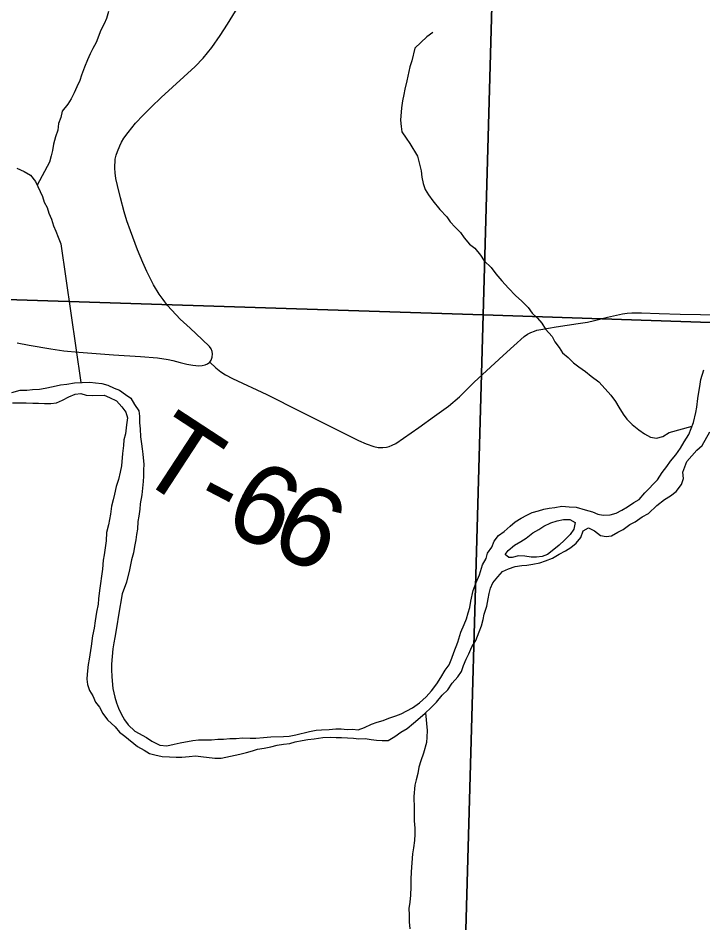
# Model space of a CAD drawing. Extents: x -3.3 to 34, y 0 to 56.8.
# Drawn here: x -1.696 to -1.207, y 30.269 to 30.915 of the extents above; entities that cross this region are included whole.
import ezdxf

# ---------------------------------------------------------------- set-up
doc = ezdxf.new("R2010")
doc.units = 0
for name, color, linetype in [('GM_X_Corporation', 7, 'Continuous'), ('GM_X_Major_River', 7, 'Continuous'), ('GM_X_State_Route', 7, 'Continuous'), ('GM_X_Township_Road', 7, 'Continuous'), ('GM_X_Township_Road_Text', 7, 'Continuous'), ('GT_Project_Soil_Layers', 7, 'Continuous')]:
    doc.layers.add(name, color=color, linetype=linetype)

msp = doc.modelspace()

# ---------------------------------------------------------------- linework, layer by layer
at = {"layer": 'GM_X_Corporation'}
for points in [[(-1.33537, 31.71163), (-1.36367, 30.70347), (-2.39277, 30.73672), (-2.35994, 31.74572)], [(-1.33537, 31.71163), (-0.3225, 31.67471), (-0.36109, 30.66979), (-1.36367, 30.70347)], [(-2.39277, 30.73672), (-1.36367, 30.70347), (-1.39177, 29.70668), (-2.4143, 29.73246)], [(-0.36109, 30.66979), (-0.38619, 29.67495), (-1.39177, 29.70668), (-1.36367, 30.70347)]]:
    msp.add_lwpolyline(points, close=True, dxfattribs=at)
at = {"layer": 'GM_X_Major_River'}
for points in [[(-1.32423, 30.56352), (-1.32046, 30.56471), (-1.31667, 30.56552), (-1.31251, 30.56596), (-1.30759, 30.56679), (-1.30228, 30.56648), (-1.29734, 30.56617), (-1.29087, 30.56437), (-1.28555, 30.56292), (-1.28173, 30.56108), (-1.27793, 30.56038), (-1.273, 30.56082), (-1.26885, 30.56202), (-1.2647, 30.56398), (-1.26056, 30.56631), (-1.25606, 30.56941), (-1.25229, 30.57174), (-1.24818, 30.57635), (-1.23921, 30.58559), (-1.23587, 30.59095), (-1.23251, 30.59517), (-1.22991, 30.599), (-1.22618, 30.60361), (-1.22283, 30.60821), (-1.22024, 30.6128), (-1.21689, 30.61816), (-1.21506, 30.62236), (-1.2136, 30.62656), (-1.2118, 30.63379), (-1.21109, 30.6376), (-1.21042, 30.64368), (-1.20972, 30.64824), (-1.20902, 30.65243), (-1.20832, 30.65737), (-1.20614, 30.66423)], [(-1.7004, 30.64817), (-1.69435, 30.64978), (-1.6898, 30.64984), (-1.68564, 30.65028), (-1.68071, 30.65035), (-1.67655, 30.65116), (-1.67088, 30.65238), (-1.66559, 30.65359), (-1.66104, 30.65404), (-1.65574, 30.65487), (-1.65006, 30.65533), (-1.64475, 30.6554), (-1.64058, 30.65508), (-1.63602, 30.65439), (-1.63184, 30.65331), (-1.62726, 30.65109), (-1.62344, 30.64963), (-1.61923, 30.64665), (-1.61541, 30.64405), (-1.61269, 30.63953), (-1.60959, 30.63502), (-1.60916, 30.63123), (-1.6091, 30.6263), (-1.60866, 30.62213), (-1.60859, 30.61644), (-1.60776, 30.61152), (-1.60733, 30.60773), (-1.6069, 30.60394), (-1.60605, 30.59674), (-1.60637, 30.59294), (-1.60631, 30.58839), (-1.60664, 30.58459), (-1.60695, 30.57965)], [(-1.69992, 30.64059), (-1.69461, 30.64066), (-1.69006, 30.64073), (-1.68551, 30.64041), (-1.68134, 30.64047), (-1.67716, 30.64015), (-1.67261, 30.64021), (-1.66845, 30.64065), (-1.6643, 30.6426), (-1.65978, 30.64495), (-1.65526, 30.64691), (-1.65109, 30.64735), (-1.64729, 30.64626), (-1.64273, 30.64594), (-1.63439, 30.64606), (-1.63058, 30.6446), (-1.62562, 30.64201), (-1.62177, 30.63789), (-1.61906, 30.63413), (-1.61787, 30.62997), (-1.61856, 30.62503), (-1.61923, 30.61857)], [(-1.61923, 30.61857), (-1.62031, 30.61438), (-1.62064, 30.6102), (-1.62132, 30.6045), (-1.62196, 30.59576), (-1.62303, 30.59119), (-1.6241, 30.58586), (-1.62593, 30.5809), (-1.62699, 30.57558), (-1.62807, 30.57139), (-1.62915, 30.56682), (-1.62983, 30.56112), (-1.63125, 30.55351), (-1.63269, 30.54817), (-1.63299, 30.5421), (-1.63437, 30.53221), (-1.63508, 30.52841), (-1.63575, 30.52195), (-1.63782, 30.50674), (-1.6385, 30.50066), (-1.63883, 30.49686), (-1.63989, 30.49115), (-1.64094, 30.48506), (-1.64163, 30.47974), (-1.6427, 30.47441), (-1.64373, 30.46681), (-1.64512, 30.45768), (-1.64583, 30.45388), (-1.6465, 30.44704), (-1.64682, 30.44324), (-1.64639, 30.43945), (-1.64482, 30.43529), (-1.6425, 30.43153), (-1.64054, 30.42701), (-1.63783, 30.42325), (-1.6355, 30.41873), (-1.63202, 30.41422), (-1.62665, 30.40936), (-1.62357, 30.40561), (-1.61973, 30.40263), (-1.61053, 30.39517), (-1.60595, 30.39258), (-1.60213, 30.39035), (-1.59832, 30.38927), (-1.593, 30.38821), (-1.58768, 30.3879), (-1.58313, 30.38758), (-1.57896, 30.38764), (-1.57366, 30.3881), (-1.56911, 30.38854), (-1.56532, 30.38821), (-1.55544, 30.38683), (-1.55089, 30.3869), (-1.53765, 30.38974), (-1.53274, 30.39095), (-1.52859, 30.39214), (-1.52481, 30.39334), (-1.52027, 30.39416), (-1.51535, 30.39499), (-1.51082, 30.39619), (-1.50628, 30.39701), (-1.50174, 30.39746), (-1.49796, 30.39865), (-1.49304, 30.39947), (-1.48888, 30.40029), (-1.48434, 30.40074), (-1.47828, 30.40158), (-1.4726, 30.40204), (-1.4688, 30.40171), (-1.46501, 30.40177), (-1.45628, 30.40113), (-1.45249, 30.4008), (-1.44793, 30.40087), (-1.44375, 30.40017), (-1.43996, 30.39984), (-1.43578, 30.39952), (-1.43161, 30.39958), (-1.42672, 30.40231), (-1.42259, 30.4054), (-1.41807, 30.40812), (-1.41358, 30.41198), (-1.40533, 30.41892), (-1.40083, 30.42316), (-1.39709, 30.42701), (-1.39299, 30.432), (-1.38887, 30.43585), (-1.3859, 30.44045), (-1.38179, 30.44506), (-1.37919, 30.44889), (-1.37773, 30.45309), (-1.37589, 30.45767), (-1.37405, 30.46149), (-1.37184, 30.46645), (-1.36887, 30.47105), (-1.36668, 30.47715), (-1.36484, 30.48135), (-1.36376, 30.48592), (-1.36305, 30.48973), (-1.36123, 30.49544), (-1.36017, 30.50077), (-1.35946, 30.50458)], [(-1.35946, 30.50458), (-1.35838, 30.50839), (-1.35691, 30.5122), (-1.35318, 30.51643), (-1.34981, 30.52027), (-1.34567, 30.52223), (-1.34076, 30.52381), (-1.33622, 30.52464), (-1.33243, 30.52469), (-1.32827, 30.52551), (-1.32335, 30.52634), (-1.3192, 30.52792), (-1.3143, 30.52988), (-1.3094, 30.53261), (-1.30489, 30.53495), (-1.30113, 30.53728), (-1.29738, 30.54037), (-1.29402, 30.54459), (-1.29219, 30.54917), (-1.28843, 30.5515), (-1.28422, 30.54928), (-1.28001, 30.54592), (-1.27583, 30.54522), (-1.27204, 30.54566), (-1.26752, 30.54838), (-1.26376, 30.55033), (-1.25888, 30.55381), (-1.25511, 30.55576), (-1.25023, 30.55925), (-1.24571, 30.56159), (-1.23972, 30.56737), (-1.23409, 30.57162), (-1.22996, 30.57433), (-1.22583, 30.57743), (-1.2221, 30.58242), (-1.22064, 30.58661), (-1.22108, 30.59116), (-1.21815, 30.59879), (-1.21106, 30.60686), (-1.20731, 30.61033), (-1.20175, 30.61989)], [(-1.60695, 30.57965), (-1.60765, 30.57509), (-1.6087, 30.56862), (-1.60903, 30.56482), (-1.60972, 30.55988), (-1.61043, 30.55607), (-1.61073, 30.55038), (-1.61144, 30.54657), (-1.61177, 30.54277), (-1.61284, 30.53821), (-1.61354, 30.53364), (-1.61499, 30.52869), (-1.61641, 30.52146), (-1.61856, 30.5127), (-1.62148, 30.50431), (-1.62431, 30.48909), (-1.62535, 30.48149), (-1.62675, 30.47312), (-1.62746, 30.46931), (-1.62816, 30.46513), (-1.62915, 30.45411), (-1.6291, 30.45032), (-1.62903, 30.445), (-1.62816, 30.43667), (-1.62694, 30.43061), (-1.62574, 30.42646), (-1.62417, 30.42268), (-1.62222, 30.41853), (-1.61989, 30.41439), (-1.61719, 30.41064), (-1.61258, 30.40615), (-1.60417, 30.40171), (-1.60035, 30.39911), (-1.59462, 30.39615), (-1.58969, 30.39584), (-1.58439, 30.39705), (-1.58023, 30.39787), (-1.57116, 30.39952), (-1.56699, 30.39996), (-1.55789, 30.40008), (-1.55335, 30.40053), (-1.54918, 30.40058), (-1.54463, 30.40103), (-1.54008, 30.40109), (-1.53554, 30.40153), (-1.53023, 30.40123), (-1.52606, 30.40129), (-1.52075, 30.40174), (-1.51545, 30.4022), (-1.50635, 30.40232), (-1.50219, 30.40276), (-1.49765, 30.40358), (-1.48782, 30.406), (-1.4829, 30.40683), (-1.47912, 30.40726), (-1.47381, 30.40733), (-1.46888, 30.40778), (-1.46509, 30.40784), (-1.46092, 30.40752), (-1.45713, 30.40757), (-1.45295, 30.40725), (-1.44842, 30.40883), (-1.44352, 30.41118), (-1.43937, 30.41275), (-1.43522, 30.41395), (-1.43107, 30.41553), (-1.42616, 30.41711), (-1.42239, 30.41868), (-1.4141, 30.42297), (-1.40922, 30.42646), (-1.40435, 30.4307), (-1.40061, 30.43493), (-1.39689, 30.43992), (-1.39392, 30.44451), (-1.39095, 30.44986), (-1.38797, 30.4537), (-1.38614, 30.45828), (-1.38468, 30.46248), (-1.38174, 30.46973), (-1.37957, 30.47697), (-1.37736, 30.48231), (-1.37552, 30.48651), (-1.37444, 30.4907), (-1.37335, 30.49451), (-1.37266, 30.49908), (-1.37087, 30.50669), (-1.36867, 30.51242), (-1.36647, 30.51776), (-1.36429, 30.525), (-1.3617, 30.52959), (-1.36061, 30.5334), (-1.35763, 30.53762), (-1.35579, 30.54182), (-1.35281, 30.54603), (-1.34868, 30.54875), (-1.34456, 30.5526), (-1.34081, 30.55569), (-1.33668, 30.55841), (-1.33253, 30.56036), (-1.32877, 30.56231), (-1.32423, 30.56352)], [(-1.34545, 30.53033), (-1.34797, 30.53234), (-1.34584, 30.53513), (-1.34134, 30.53899), (-1.33683, 30.54171), (-1.33307, 30.54404), (-1.32819, 30.5479), (-1.32405, 30.55024), (-1.32029, 30.55257), (-1.31539, 30.55491), (-1.31087, 30.5565), (-1.30633, 30.55732), (-1.30178, 30.55738), (-1.29795, 30.55516), (-1.29903, 30.55059), (-1.30163, 30.54676), (-1.30575, 30.54253), (-1.30949, 30.53906), (-1.31324, 30.53597), (-1.31775, 30.53249), (-1.32152, 30.53092), (-1.32568, 30.53048), (-1.32947, 30.53043), (-1.33403, 30.53112), (-1.33859, 30.53143), (-1.34312, 30.53023), (-1.34547, 30.53033)]]:
    msp.add_lwpolyline(points, dxfattribs=at)
at = {"layer": 'GM_X_State_Route'}
msp.add_lwpolyline([(-1.69652, 30.68365), (-1.68799, 30.68187), (-1.67261, 30.67922), (-1.66332, 30.6779), (-1.65248, 30.67686), (-1.62789, 30.67486), (-1.60841, 30.67371), (-1.59627, 30.67281), (-1.58868, 30.67157), (-1.58542, 30.67085), (-1.58005, 30.6696), (-1.57538, 30.66835), (-1.57109, 30.66754), (-1.56682, 30.66713), (-1.56443, 30.6673), (-1.56235, 30.66778), (-1.56057, 30.66856), (-1.559, 30.6698), (-1.55807, 30.67126), (-1.55736, 30.67338), (-1.55703, 30.67568), (-1.55728, 30.67733), (-1.5581, 30.67938), (-1.55926, 30.68086), (-1.56435, 30.68604), (-1.57298, 30.69393), (-1.58007, 30.70054), (-1.58911, 30.71024), (-1.59238, 30.71441), (-1.59512, 30.71831), (-1.59922, 30.72496), (-1.60397, 30.73454), (-1.60693, 30.74103), (-1.61063, 30.75007), (-1.61565, 30.76364), (-1.61819, 30.77063), (-1.62015, 30.77705), (-1.62288, 30.78707), (-1.62502, 30.79594), (-1.62601, 30.80087), (-1.62658, 30.80499), (-1.62674, 30.80819), (-1.6265, 30.81467), (-1.62584, 30.8175), (-1.62504, 30.82011), (-1.62336, 30.82433), (-1.62207, 30.8269), (-1.62038, 30.82971), (-1.6174, 30.83375), (-1.61203, 30.84033), (-1.60665, 30.84603), (-1.60062, 30.85219), (-1.59372, 30.85871), (-1.56934, 30.88096), (-1.56366, 30.88685), (-1.55764, 30.89443), (-1.55153, 30.90297), (-1.54626, 30.91101), (-1.53672, 30.92652)], dxfattribs=at)
at = {"layer": 'GM_X_Township_Road'}
msp.add_lwpolyline([(-1.559, 30.6698), (-1.55469, 30.66564), (-1.55104, 30.66284), (-1.54789, 30.66079), (-1.5427, 30.65797), (-1.51837, 30.64669), (-1.49412, 30.63447), (-1.45285, 30.61384), (-1.4474, 30.61149), (-1.44181, 30.60942), (-1.43873, 30.60882), (-1.43551, 30.60872), (-1.43268, 30.60906), (-1.43099, 30.60954), (-1.42878, 30.61036), (-1.42607, 30.61167), (-1.40966, 30.62316), (-1.39848, 30.63121), (-1.38854, 30.63837), (-1.38068, 30.64505), (-1.37012, 30.65545), (-1.36126, 30.66359), (-1.34944, 30.67446), (-1.34184, 30.68143), (-1.33445, 30.68802), (-1.332, 30.68975), (-1.32972, 30.69092), (-1.32713, 30.69195), (-1.32534, 30.69251), (-1.32262, 30.69312), (-1.31168, 30.69505), (-1.2959, 30.69734), (-1.28912, 30.69841), (-1.28417, 30.69955), (-1.27486, 30.70189), (-1.26839, 30.70341), (-1.26411, 30.70431), (-1.26083, 30.70481), (-1.25745, 30.70497), (-1.25063, 30.70489), (-1.23797, 30.70448), (-1.2231, 30.7041), (-1.20854, 30.70372), (-1.1935, 30.70333)], dxfattribs=at)
at = {"layer": 'GT_Project_Soil_Layers'}
for points in [[(-1.63127, 30.92011), (-1.63271, 30.91516), (-1.63456, 30.91134), (-1.63677, 30.90675), (-1.64007, 30.89798), (-1.64266, 30.89377), (-1.64451, 30.88994), (-1.64635, 30.88575), (-1.64855, 30.8804), (-1.65075, 30.87468), (-1.65183, 30.87087), (-1.65405, 30.86628), (-1.65589, 30.86208), (-1.6581, 30.85787), (-1.66033, 30.85405), (-1.66443, 30.84906), (-1.66551, 30.84449), (-1.66697, 30.84029), (-1.66766, 30.83535), (-1.66912, 30.83077), (-1.67056, 30.82544), (-1.67126, 30.82088), (-1.67234, 30.81707), (-1.67342, 30.8125), (-1.68228, 30.79621)], [(-1.39975, 30.90515), (-1.40388, 30.90206), (-1.4125, 30.89396), (-1.41465, 30.88482), (-1.41611, 30.88063), (-1.41825, 30.87073), (-1.41968, 30.86464), (-1.42039, 30.86083), (-1.42147, 30.85626), (-1.42216, 30.85132), (-1.4228, 30.84258), (-1.42236, 30.83803), (-1.42193, 30.83425), (-1.41883, 30.82974), (-1.41613, 30.82598), (-1.4107, 30.81695), (-1.4079, 30.80636), (-1.40746, 30.80181), (-1.40664, 30.79727), (-1.40507, 30.79312), (-1.40274, 30.78935), (-1.39965, 30.78484), (-1.39464, 30.77884), (-1.38963, 30.7736), (-1.38731, 30.76984), (-1.38385, 30.76609), (-1.38, 30.76235), (-1.3773, 30.75859), (-1.37345, 30.75409), (-1.36961, 30.75111), (-1.36575, 30.74623), (-1.36305, 30.74209), (-1.35805, 30.73723), (-1.35458, 30.73273), (-1.35034, 30.72785), (-1.34572, 30.7226), (-1.34072, 30.71736), (-1.33611, 30.71325), (-1.3315, 30.70876), (-1.32879, 30.70463), (-1.32495, 30.70127), (-1.32187, 30.69751), (-1.31916, 30.69338), (-1.31454, 30.68813), (-1.31259, 30.68436), (-1.3095, 30.68023), (-1.30717, 30.67647), (-1.30296, 30.67311), (-1.29912, 30.66937), (-1.29528, 30.66639), (-1.29069, 30.66304), (-1.28647, 30.65968), (-1.28111, 30.65558), (-1.27649, 30.65071), (-1.27264, 30.64622), (-1.26916, 30.64171), (-1.26684, 30.63757), (-1.26374, 30.63268), (-1.26103, 30.62892), (-1.25719, 30.62518), (-1.25259, 30.62145), (-1.24838, 30.61847), (-1.24417, 30.61626), (-1.23999, 30.61556), (-1.23546, 30.61676), (-1.23095, 30.61948), (-1.21447, 30.62405)], [(-1.69687, 30.80837), (-1.69153, 30.80579), (-1.68695, 30.8032), (-1.68347, 30.79869), (-1.6784, 30.78814), (-1.6772, 30.78398), (-1.67526, 30.78021), (-1.67406, 30.77606)], [(-1.67406, 30.77606), (-1.67211, 30.77191), (-1.67053, 30.767), (-1.66896, 30.76322), (-1.66739, 30.75907), (-1.66543, 30.75416), (-1.65109, 30.65525)], [(-1.40494, 30.41929), (-1.40365, 30.4068), (-1.40396, 30.40187), (-1.40429, 30.39807), (-1.40646, 30.39045), (-1.40828, 30.38511), (-1.40974, 30.38053), (-1.41044, 30.37597), (-1.41151, 30.3714), (-1.4126, 30.36759), (-1.41325, 30.35961), (-1.41313, 30.35089), (-1.41302, 30.34216), (-1.41256, 30.33685), (-1.41251, 30.33268), (-1.41283, 30.32812), (-1.41351, 30.3228), (-1.41421, 30.31861), (-1.41518, 30.3057), (-1.41549, 30.30038), (-1.41541, 30.29507), (-1.41571, 30.289), (-1.41602, 30.28406), (-1.41672, 30.27949), (-1.41666, 30.27494), (-1.41659, 30.27001), (-1.41615, 30.26508)]]:
    msp.add_lwpolyline(points, dxfattribs=at)

# ---------------------------------------------------------------- texts
at = {"layer": 'GM_X_Township_Road_Text'}
for s, rotation, p in [('T', 326.83887, (-1.614, 30.58956)), ('6', 333.72372, (-1.55128, 30.55183)), ('-', 332.41981, (-1.57322, 30.56327)), ('6', 335.11917, (-1.51853, 30.53568))]:
    msp.add_text(s, height=0.05682, rotation=rotation, dxfattribs=at).set_placement(p)

doc.saveas('drawing.dxf')
